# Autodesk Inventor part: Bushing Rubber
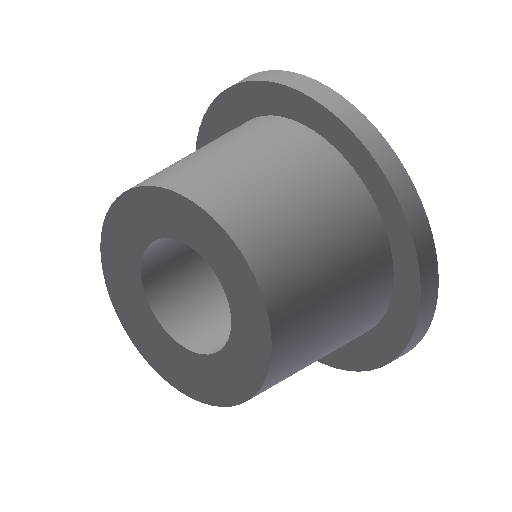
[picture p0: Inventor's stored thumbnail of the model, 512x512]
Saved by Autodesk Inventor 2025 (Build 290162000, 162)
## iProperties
Created: 2010-03
Part Number: Bushing Rubber
Document SubType Name: Modeling
Designer: bhakira
Density: 1 g/cm^3
Material: Generic
Appearance: Default
Author: bhakira
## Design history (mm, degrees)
sketch "Sketch1"
  geometry: L1 (25, 31)-(25, 27); L2 (25, 27)-(19, 27); L3 (19, 27)-(19, 0); L4 (19, 0)-(0, 0); L5 (0, 0)-(0, 31); L6 (0, 31)-(25, 31); 1 further point
  constraints: 12 end point, 1 coincident, 1 other
  dimensions: "d1" = 50 diameter of L1 L5; "d2" = 38 diameter of L3 L5; "d3" = 4 distance of L1.start L1.end; "d4" = 27 distance between parallel lines of L4 L2
revolve "Revolution1" sketch "Sketch1" stored, may be unused: angle "d5" = 90 deg
hole "Hole1" diameter "d8" = 20; stored, may be unused: countersink angle "d12" = 82 deg, drill point angle "d14" = 118 deg; dims "d6" = 10, "d7" = 10, "d9" = 6, "d10" = 34.925, "d11" = 2, "d13" = 8
body "Solid1"
